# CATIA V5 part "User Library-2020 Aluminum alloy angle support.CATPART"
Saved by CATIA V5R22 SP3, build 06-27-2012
Part number: 4DB69303-F3E1-4FCE-AF6C-4B57F02163B2
Revision: ANY
Definition: UNKNOWN
Nomenclature: 4DB69303-F3E1-4FCE-AF6C-4B57F02163B2
Source: Unknown
Bounding box of the stored display mesh (mm): x 0 to 20, y -10.677 to 19.323, z -21.469 to 8.531
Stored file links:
  \\PSSILO\catalogs\ContentCentral\2020 Aluminum alloy angle support\Cache\4DB69303-F3E1-4FCE-AF6C-4B57F02163B2.CATPart
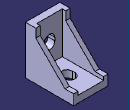
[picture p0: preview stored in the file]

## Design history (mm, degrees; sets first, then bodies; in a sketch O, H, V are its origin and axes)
Body1 "??-??6" (main body)
  Solid1: solid without history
